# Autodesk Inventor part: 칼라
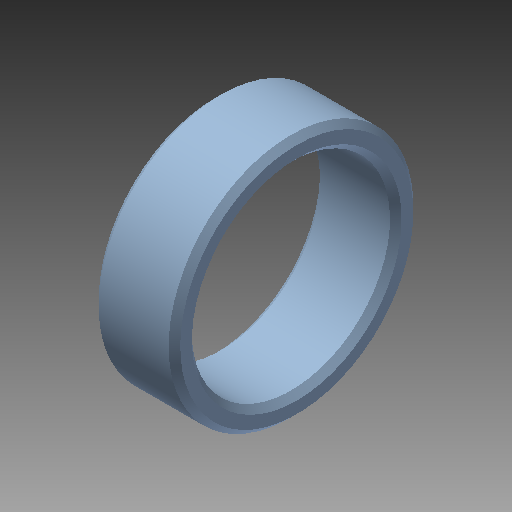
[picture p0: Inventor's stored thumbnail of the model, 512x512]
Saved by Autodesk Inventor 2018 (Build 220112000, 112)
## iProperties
Created: 2024-01
Part Number: 칼라
Material: 강철, 합금
Document SubType Name: Modeling
Designer: mdu-01
Density: 1 g/cm^3
Appearance: 기본값(1)
Author: mdu-01
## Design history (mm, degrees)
sketch "스케치1"
  geometry: L1 (-3.5, 0)-(3.5, 0); L2 (-3, 8.5)-(3, 8.5); L3 (3.5, 9)-(3.5, 10); L4 (3, 10.5)-(-3, 10.5); L5 (-3.5, 10)-(-3.5, 9); L6 (-3, 10.5)-(-3.5, 10); L7 (-3, 8.5)-(-3.5, 9); L8 (3, 8.5)-(3.5, 9); L9 (3.5, 10)-(3, 10.5); 6 further points
  constraints: 18 end point, 10 point on line, 2 horizontal, 2 parallel, 1 coincident, 1 midpoint, 1 perpendicular
  dimensions: "d0" = 7 distance of L1.start L1.end; "d1" = 17 diameter of L2 L1; "d2" = 2 distance between parallel lines of L4 L2; "d3" = 0.5 distance of L4.end point (-3.5, 10.5); "d4" = 0.5 distance of L5.start point (-3.5, 10.5) (= d3); "d5" = 0.5 distance of L2.start point (-3.5, 8.5) (= d3); "d6" = 0.5 distance of L5.end point (-3.5, 8.5) (= d5); "d7" = 0.5 distance of L2.end point (3.5, 8.5) (= d3); "d8" = 0.5 distance of L3.start point (3.5, 8.5) (= d7); "d9" = 0.5 distance of L3.end point (3.5, 10.5) (= d3); "d10" = 0.5 distance of L4.start point (3.5, 10.5) (= d9)
revolve "회전1" sketch "스케치1" stored, may be unused: angle "d11" = 90 deg
node "솔리드1"
